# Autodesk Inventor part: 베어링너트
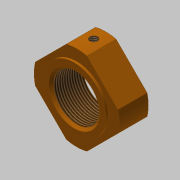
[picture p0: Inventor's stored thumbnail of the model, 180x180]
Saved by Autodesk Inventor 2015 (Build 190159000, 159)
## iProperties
Created: 2019-05
Part Number: 베어링너트
Material: 스테인리스강
Document SubType Name: Modeling
Designer: mduedu
Density: 1 g/cm^3
Appearance: 주황색
Author: mduedu
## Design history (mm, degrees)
sketch "스케치1"
  geometry: C1 r 17.5 at (0, 0); 1 further point
  constraints: 1 centre point, 1 coincident
  dimensions: "d0" = 35 diameter of C1
extrude "돌출1" new body sketch "스케치1" distance "d1" = 12; taper "d2" = 0 deg
sketch "스케치2"
  geometry: L1 (-21.213, 0)-(0, 21.213); L2 (0, 21.213)-(21.213, 0); L3 (21.213, 0)-(0, -21.213); L4 (0, -21.213)-(-21.213, 0); L5 (-21.213, 0)-(21.213, 0); L6 (0, 21.213)-(0, -21.213); 1 further point
  constraints: 12 end point, 2 midpoint, 2 parallel, 1 perpendicular, 1 vertical
  dimensions: "d3" = 30 distance of L1.end L2.end; "d5" = 30 distance of L2.end L3.end
extrude "돌출2" sketch "스케치2" stored distance "d6" = 12; taper "d7" = 0 deg
sketch "스케치3"
  geometry: C1 r 13 at (0, 0); 1 further point
  constraints: 1 centre point, 1 coincident
  dimensions: "d8" = 26 diameter of C1
extrude "돌출3" join sketch "스케치3" distance "d9" = 1; taper "d10" = 0 deg
hole "구멍1" diameter "d13" = 18.917; stored, may be unused: countersink angle "d17" = 90 deg, drill point angle "d19" = 118 deg; dims "d11" = 10, "d12" = 10, "d14" = 6, "d15" = 4, "d16" = 2, "d18" = 8
chamfer "모따기1" distance "d20" = 1; stored, may be unused: second distance "d21" = 2, angle "d22" = 45 deg
node "작업 평면1"
sketch "스케치5"
  geometry: L1 (-4.233, 0)-(4.233, 0) reference; 3 further points
  constraints: 1 midpoint, 1 vertical alignment
  dimensions: "d31" = 5 distance from line of point (0, 5) L1
hole "구멍3" sketch "스케치5" at (0, 5) diameter "d32" = 3.242; stored, may be unused: countersink angle "d36" = 90 deg, drill point angle "d38" = 118 deg; dims "d33" = 6, "d34" = 4, "d35" = 2, "d37" = 8
node "솔리드1"
